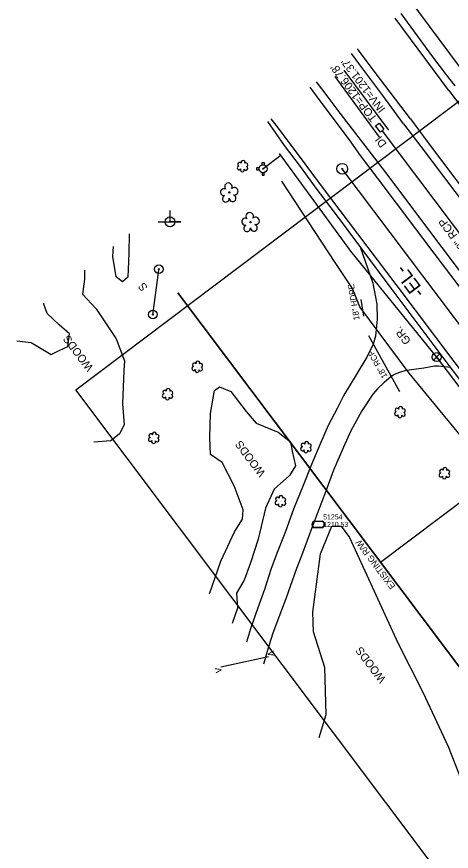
# Model space of a CAD drawing. Extents: x 1262092 to 1264624, y 774970 to 778314.
# Drawn here: x 1262092.3 to 1262309.6, y 777671.7 to 778088.7 of the extents above; entities that cross this region are included whole.
import ezdxf

# ---------------------------------------------------------------- set-up
doc = ezdxf.new("R2010")
doc.units = 0
for name, color, linetype in [('COGO Default Parcel', 7, 'Continuous'), ('Exist Boundary City Limits', 7, 'Continuous'), ('Exist Horizontal Alignment', 7, 'Continuous'), ('Exist Horizontal Alignment Direction Label', 7, 'Continuous'), ('Exist Horizontal Alignment Station Label', 7, 'Continuous'), ('Exist Horizontal Alignment Tick Label', 7, 'Continuous'), ('Exist Horizontal Alignment Tick Large', 7, 'Continuous'), ('Exist Horizontal Alignment Tick Small', 7, 'Continuous'), ('Exist Right of Way Line', 7, 'Continuous'), ('Exist Right of Way Line Text', 7, 'Continuous'), ('Exist Right of Way Width CELL', 7, 'Continuous'), ('Exist Roads EOP', 7, 'Continuous'), ('Exist Roads EOT', 7, 'Continuous'), ('Exist Roads Soil Text', 7, 'Continuous'), ('Exist Structure Minor Drop Inlet', 7, 'Continuous'), ('Exist Structure Minor Drop Inlet Text', 7, 'Continuous'), ('Exist Structure Minor Drop Inlet Top Elevation', 7, 'Continuous'), ('Exist Structure Minor Paved Ditch or Gutter', 7, 'Continuous'), ('Exist Structure Minor Pipes HDPE 18 Inch', 7, 'Continuous'), ('Exist Structure Minor Pipes HDPE 18 Inch Text', 7, 'Continuous'), ('Exist Structure Minor Pipes RCP 18 Inch', 7, 'Continuous'), ('Exist Structure Minor Pipes RCP 18 Inch Invert', 7, 'Continuous'), ('Exist Structure Minor Pipes RCP 18 Inch Text', 7, 'Continuous'), ('Exist Utilities Power Joint Use Telephone CELL', 7, 'Continuous'), ('Exist Utilities Sanitary Sewer UG Line', 7, 'Continuous'), ('Exist Utilities Telephone UG FO SUE LOS B', 7, 'Continuous'), ('Exist Utilities Water Fire Hydrant CELL', 7, 'Continuous'), ('Exist Utilities Water Meter CELL', 7, 'Continuous'), ('Exist Utilities Water Meter Cogo Elevation', 7, 'Continuous'), ('Exist Utilities Water Meter Cogo Number', 7, 'Continuous'), ('Exist Utilities Water UG Line SUE LOS B', 7, 'Continuous'), ('Exist Utilities Water Valve CELL', 7, 'Continuous'), ('Exist Vegetation Woods Line Text', 7, 'Continuous'), ('Prop Conc 5in Monolithic Keyed In Island', 7, 'Continuous'), ('Prop Conc 5in Monolithic Surface Mount Island', 7, 'Continuous'), ('Prop Horizontal Alignment Tick Small', 7, 'Continuous'), ('Prop Paved Shoulder', 7, 'Continuous'), ('Scratch_Level_1', 7, 'Continuous')]:
    doc.layers.add(name, color=color, linetype=linetype)

# ---------------------------------------------------------------- blocks, each defined once
blk = doc.blocks.new('EXIST UTILITIES WATER VALVE')
at = {"layer": 'Exist Utilities Water Valve CELL'}
blk.add_lwpolyline([(0.0315, 0.0315), (-0.0315, -0.0315), (0, 0), (0.0315, -0.0315), (-0.0315, 0.0315)], dxfattribs=at)
blk.add_circle((0, 0), 0.0445, dxfattribs=at)
blk = doc.blocks.new('EXIST UTILITIES WATER FIRE HYDRANT')
at = {"layer": 'Exist Utilities Water Fire Hydrant CELL'}
blk.add_line((0, 0), (0, 0), dxfattribs=at)
for points in [[(-0.03825, 0.01025), (-0.064, 0.01025), (-0.064, -0.01025), (-0.03825, -0.01025)], [(-0.01025, 0.03825), (-0.01025, 0.064), (0.01025, 0.064), (0.01025, 0.03775)], [(-0.01025, -0.03825), (-0.01025, -0.064), (0.01025, -0.064), (0.01025, -0.03775)]]:
    blk.add_lwpolyline(points, dxfattribs=at)
for radius in [0.03954, 0.00485]:
    blk.add_circle((0, 0), radius, dxfattribs=at)
blk = doc.blocks.new('EXIST UTILITIES WATER METER')
at = {"layer": 'Exist Utilities Water Meter CELL'}
blk.add_line((0, 0), (0, 0), dxfattribs=at)
for points in [[(-0.0408, 0.034), (0.0408, 0.034)], [(-0.0408, 0.0312), (0.0408, 0.0312)], [(0.0408, -0.0312), (-0.0413, -0.0312)], [(0.0408, -0.034), (-0.0413, -0.034)]]:
    blk.add_lwpolyline(points, dxfattribs=at)
for centre, radius, start, end in [((-0.0261, -0.0001), 0.0371, 113.17804, 245.97939), ((-0.0259, -0.0001), 0.0347, 115.30093, 243.78236), ((0.0259, 0), 0.0371, 293.64832, 66.30838), ((0.0261, 0), 0.0345, 295.12717, 64.87283)]:
    blk.add_arc(centre, radius, start, end, dxfattribs=at)

msp = doc.modelspace()

# ---------------------------------------------------------------- linework, layer by layer
at = {"layer": 'COGO Default Parcel'}
for p, q in [((1262121.77, 777902.18), (1262441.33, 778142.77)), ((1263155.86, 776528.63), (1262121.77, 777902.18))]:
    msp.add_line(p, q, dxfattribs=at)
at = {"layer": 'Exist Boundary City Limits'}
msp.add_line((1263013.39, 776834.66), (1262172.78, 777950.69), dxfattribs=at)
at = {"layer": 'Exist Horizontal Alignment'}
msp.add_line((1264460.35, 775084.79), (1262255.05, 778012.66), dxfattribs=at)
at = {"layer": 'Exist Horizontal Alignment Station Label'}
msp.add_line((1262160.42, 777939.68), (1262163.43, 777962.08), dxfattribs=at)
for centre, radius in [((1262163.35, 777962.55), 2.18), ((1262163.35, 777962.55), 0.24), ((1262160.39, 777939.84), 2.18), ((1262160.39, 777939.84), 0.24)]:
    msp.add_circle(centre, radius, dxfattribs=at)
at = {"layer": 'Exist Horizontal Alignment Tick Label'}
for radius in [2.71, 0.187]:
    msp.add_circle((1262255.05, 778012.66), radius, dxfattribs=at)
at = {"layer": 'Exist Horizontal Alignment Tick Large'}
for p, q in [((1262205.25, 778013.8), (1262205.25, 778013.8)), ((1262182.59, 777913.56), (1262182.59, 777913.56)), ((1262167.75, 777899.89), (1262167.75, 777899.89)), ((1262284, 777890.93), (1262284, 777890.93)), ((1262160.86, 777878.12), (1262160.86, 777878.12)), ((1262237, 777873.43), (1262237, 777873.43)), ((1262306.24, 777860.38), (1262306.24, 777860.38)), ((1262224.21, 777846.48), (1262224.21, 777846.48))]:
    msp.add_line(p, q, dxfattribs=at)
for centre, radius, start, end in [((1262205.48, 778015.84), 0.99, 334.8391, 200.4717), ((1262203.45, 778013.09), 0.955, 95.1099, 327.9534), ((1262203.77, 778014.92), 0.968, 35.8908, 245.4216), ((1262206.89, 778012.87), 0.937, 204.9913, 73.4601), ((1262206.92, 778014.67), 0.929, 284.4567, 126.0861), ((1262205.12, 778012.11), 0.984, 151.2797, 21.387), ((1262180.79, 777912.86), 0.955, 95.1099, 327.9534), ((1262181.11, 777914.69), 0.968, 35.8908, 245.4216), ((1262182.82, 777915.6), 0.99, 334.8391, 200.4717), ((1262184.23, 777912.63), 0.937, 204.9913, 73.4601), ((1262184.27, 777914.43), 0.929, 284.4567, 126.0861), ((1262182.47, 777911.88), 0.984, 151.2797, 21.387), ((1262165.95, 777899.18), 0.955, 95.1099, 327.9534), ((1262166.27, 777901.01), 0.968, 35.8908, 245.4216), ((1262167.98, 777901.93), 0.99, 334.8391, 200.4717), ((1262169.42, 777900.76), 0.929, 284.4567, 126.0861), ((1262167.62, 777898.2), 0.984, 151.2797, 21.387), ((1262169.39, 777898.96), 0.937, 204.9913, 73.4601), ((1262282.52, 777892.06), 0.968, 35.8908, 245.4216), ((1262284.23, 777892.97), 0.99, 334.8391, 200.4717), ((1262285.68, 777891.8), 0.929, 284.4567, 126.0861), ((1262282.2, 777890.23), 0.955, 95.1099, 327.9534), ((1262283.88, 777889.25), 0.984, 151.2797, 21.387), ((1262285.64, 777890.01), 0.937, 204.9913, 73.4601), ((1262159.38, 777879.25), 0.968, 35.8908, 245.4216), ((1262161.09, 777880.16), 0.99, 334.8391, 200.4717), ((1262162.54, 777878.99), 0.929, 284.4567, 126.0861), ((1262159.06, 777877.41), 0.955, 95.1099, 327.9534), ((1262160.73, 777876.43), 0.984, 151.2797, 21.387), ((1262162.5, 777877.19), 0.937, 204.9913, 73.4601), ((1262235.52, 777874.56), 0.968, 35.8908, 245.4216), ((1262237.23, 777875.47), 0.99, 334.8391, 200.4717), ((1262238.68, 777874.3), 0.929, 284.4567, 126.0861), ((1262235.2, 777872.72), 0.955, 95.1099, 327.9534), ((1262236.88, 777871.74), 0.984, 151.2797, 21.387), ((1262238.64, 777872.5), 0.937, 204.9913, 73.4601), ((1262306.46, 777862.42), 0.99, 334.8391, 200.4717), ((1262304.43, 777859.67), 0.955, 95.1099, 327.9534), ((1262304.75, 777861.5), 0.968, 35.8908, 245.4216), ((1262306.11, 777858.69), 0.984, 151.2797, 21.387), ((1262307.87, 777859.45), 0.937, 204.9913, 73.4601), ((1262307.91, 777861.25), 0.929, 284.4567, 126.0861), ((1262222.41, 777845.78), 0.955, 95.1099, 327.9534), ((1262222.73, 777847.61), 0.968, 35.8908, 245.4216), ((1262224.44, 777848.52), 0.99, 334.8391, 200.4717), ((1262225.85, 777845.55), 0.937, 204.9913, 73.4601), ((1262225.88, 777847.35), 0.929, 284.4567, 126.0861), ((1262224.08, 777844.8), 0.984, 151.2797, 21.387)]:
    msp.add_arc(centre, radius, start, end, dxfattribs=at)
at = {"layer": 'Exist Horizontal Alignment Tick Small'}
for p, q in [((1262198.55, 778000.85), (1262198.55, 778000.85)), ((1262209.18, 777986.05), (1262209.18, 777986.05))]:
    msp.add_line(p, q, dxfattribs=at)
for centre in [(1262198.55, 778000.85), (1262209.18, 777986.05)]:
    msp.add_circle(centre, 0.326, dxfattribs=at)
for centre, radius, start, end in [((1262198.16, 778003.72), 1.86, 330.1651, 219.7134), ((1262195.94, 778001), 1.73, 62.6636, 279.3457), ((1262201.1, 778001.44), 1.9, 257.1011, 134.1999), ((1262196.85, 777997.73), 1.69, 111.5671, 6.231), ((1262200.22, 777997.95), 1.7, 181.2822, 74.56), ((1262206.57, 777986.2), 1.73, 62.6636, 279.3457), ((1262208.79, 777988.92), 1.86, 330.1651, 219.7134), ((1262211.72, 777986.64), 1.9, 257.1011, 134.1999), ((1262207.47, 777982.93), 1.69, 111.5671, 6.231), ((1262210.85, 777983.15), 1.7, 181.2822, 74.56)]:
    msp.add_arc(centre, radius, start, end, dxfattribs=at)
at = {"layer": 'Exist Right of Way Line'}
msp.add_line((1262172.78, 777950.69), (1263224.83, 776553.94), dxfattribs=at)
at = {"layer": 'Exist Right of Way Width CELL'}
msp.add_line((1262274.14, 777816.12), (1262377.95, 777894.31), dxfattribs=at)
at = {"layer": 'Exist Roads EOP'}
for points in [[(1262311.57, 778054.09), (1262307.15, 778059.68), (1262299.95, 778069.33), (1262289.62, 778083.4), (1262284.54, 778090.33)], [(1262285.77, 778035.09), (1262275.45, 778049.22), (1262263.83, 778064.64), (1262259.68, 778070.19)], [(1262268.09, 778022.33), (1262253.95, 778040.53), (1262247.45, 778049.14), (1262242.22, 778056.05)], [(1262242.02, 778002.99), (1262234.65, 778013.07), (1262226.25, 778024.29), (1262217.88, 778036.33)], [(1262285.77, 778035.09), (1262294.3, 778023.82), (1262322.73, 777986.32), (1262351.06, 777948.49), (1262379.86, 777910.83), (1262408.98, 777872.17), (1262437.51, 777834.34), (1262465.79, 777796.98), (1262494.21, 777759.25), (1262523.56, 777720.28), (1262551.17, 777683.56), (1262580.06, 777645.73)], [(1262533.86, 777669.85), (1262506.16, 777706.68), (1262477.25, 777744.96), (1262448.83, 777782.76), (1262448.77, 777782.75), (1262419.94, 777820.99), (1262391.44, 777858.59), (1262362.67, 777897.37), (1262333.74, 777935.31), (1262305.02, 777973.3), (1262276.84, 778010.82), (1262268.09, 778022.33)], [(1262508.59, 777649.5), (1262480.62, 777686.61), (1262451.55, 777725.45), (1262423.03, 777763.23), (1262394.37, 777801.14), (1262366.02, 777838.6), (1262337.3, 777876.52), (1262308.59, 777914.31), (1262279.57, 777952.95), (1262251.16, 777991.02), (1262242.02, 778002.99)]]:
    msp.add_lwpolyline(points, dxfattribs=at)
at = {"layer": 'Exist Roads EOT'}
for points in [[(1262308.34, 778051.79), (1262293.03, 778072.51), (1262281.51, 778087.87)], [(1262289.2, 778037.57), (1262271.58, 778060.8), (1262262.68, 778072.62)], [(1262264.28, 778019.28), (1262258.72, 778027.11), (1262243.53, 778047.28), (1262238.95, 778053.39)], [(1262308.34, 778051.79), (1262317.32, 778039.93), (1262344.37, 778004.19), (1262372.89, 777966.62), (1262401.21, 777929.2), (1262429.93, 777891.21), (1262458.73, 777853.38), (1262487.94, 777814.62), (1262517.12, 777776.18), (1262546.22, 777737.8), (1262573.92, 777700.82), (1262602.3, 777663.12)], [(1262244.27, 778004.78), (1262232.65, 778020.23), (1262221.97, 778034.53), (1262219.58, 778037.7)], [(1262289.2, 778037.57), (1262297.52, 778026.31), (1262325.76, 777988.99), (1262354.59, 777951.12), (1262382.95, 777913.24), (1262412.22, 777874.41), (1262440.97, 777836.5), (1262469.27, 777799.15), (1262497.42, 777761.79), (1262526.95, 777722.8), (1262554.72, 777686.15), (1262583.3, 777648.11)], [(1262530.21, 777667.14), (1262502.53, 777703.54), (1262473.57, 777742.17), (1262445.07, 777779.99), (1262416.17, 777818.02), (1262387.95, 777855.59), (1262358.59, 777894.64), (1262330.16, 777932.09), (1262301.01, 777970.53), (1262273.04, 778007.62), (1262264.28, 778019.28)], [(1262511.28, 777651.42), (1262483.32, 777688.89), (1262454.05, 777727.36), (1262425.45, 777765.13), (1262396.78, 777803.08), (1262368.42, 777840.5), (1262339.71, 777878.55), (1262311.54, 777915.71), (1262282.01, 777954.91), (1262253.58, 777992.51), (1262244.27, 778004.78)]]:
    msp.add_lwpolyline(points, dxfattribs=at)
at = {"layer": 'Exist Structure Minor Drop Inlet'}
msp.add_lwpolyline([(1262275.95, 778032.42), (1262274.13, 778031.01), (1262271.73, 778034.1), (1262273.55, 778035.51), (1262275.95, 778032.42)], dxfattribs=at)
at = {"layer": 'Exist Structure Minor Paved Ditch or Gutter'}
for p, q in [((1262273.73, 778028.5), (1262251.46, 778058.71)), ((1262278.42, 778031.97), (1262256, 778062))]:
    msp.add_line(p, q, dxfattribs=at)
at = {"layer": 'Exist Structure Minor Pipes HDPE 18 Inch'}
msp.add_line((1262264.3, 777947.43), (1262265.64, 777939.06), dxfattribs=at)
at = {"layer": 'Exist Structure Minor Pipes RCP 18 Inch'}
for p, q in [((1262514.1, 777714.3), (1262275, 778031.81)), ((1262283.95, 777901.25), (1262268.3, 777929.16))]:
    msp.add_line(p, q, dxfattribs=at)
at = {"layer": 'Exist Utilities Power Joint Use Telephone CELL'}
msp.add_line((1262168.96, 777986.16), (1262168.96, 777986.16), dxfattribs=at)
msp.add_lwpolyline([(1262163.02, 777986.16), (1262174.36, 777986.12), (1262168.96, 777986.14), (1262168.96, 777991.78)], dxfattribs=at)
msp.add_circle((1262168.96, 777986.16), 2.45, dxfattribs=at)
at = {"layer": 'Exist Utilities Sanitary Sewer UG Line'}
msp.add_line((1262150.97, 778282.31), (1262537.27, 777762.91), dxfattribs=at)
at = {"layer": 'Exist Utilities Telephone UG FO SUE LOS B'}
msp.add_lwpolyline([(1262497.69, 777644.72), (1262472.81, 777678.82), (1262454.22, 777702.45), (1262410.39, 777767.02), (1262381.85, 777803.45), (1262346.33, 777843.25), (1262319.52, 777872.83), (1262288.46, 777910.54), (1262263.91, 777943.64), (1262260.24, 777952.77), (1262251.56, 777965.81), (1262224.91, 778006.43)], dxfattribs=at)
at = {"layer": 'Exist Utilities Water UG Line SUE LOS B'}
msp.add_line((1262224.43, 778019.24), (1262215.47, 778012.68), dxfattribs=at)
msp.add_lwpolyline([(1262961.53, 777041.32), (1262916.91, 777099.45), (1262892.75, 777131.3), (1262862.6, 777171.1), (1262817.98, 777226.85), (1262789.55, 777268.74), (1262774.27, 777287.66), (1262763.83, 777305.05), (1262732.33, 777346.94), (1262685.88, 777410.11), (1262660.87, 777443.18), (1262632.31, 777481.08), (1262598.3, 777526.4), (1262560.14, 777576.52), (1262506.51, 777647.45), (1262479.01, 777683.48), (1262453.07, 777718.25), (1262416.94, 777766.02), (1262382.77, 777811.78), (1262358.61, 777844.73), (1262327.38, 777885.68), (1262302.32, 777918.54), (1262259.45, 777971.43), (1262223.66, 778020.3)], dxfattribs=at)
at = {"layer": 'Prop Conc 5in Monolithic Keyed In Island'}
for points in [[(1262148.48, 777980.09), (1262148.38, 777970.54), (1262147.92, 777958.5), (1262145.15, 777956.26), (1262141.94, 777958.67), (1262140.4, 777968.87), (1262140.73, 777973.82)], [(1262126.22, 777962.06), (1262126.2, 777957.44), (1262125.1, 777950.08), (1262132.04, 777942.64), (1262142.04, 777927.73), (1262146.11, 777916.75), (1262145.89, 777911.8), (1262145.26, 777895.21), (1262146.06, 777884.81), (1262143.76, 777880.27), (1262139.27, 777876.76), (1262130.87, 777876.12)], [(1262092.26, 777926.7), (1262099.45, 777925.9), (1262109.44, 777919.84), (1262113.53, 777921.82), (1262117.89, 777923.81), (1262118.69, 777930.26), (1262113.47, 777934.71), (1262107.49, 777940.38), (1262105.84, 777945), (1262105.82, 777945.54)], [(1262188.74, 777800.31), (1262194.36, 777816.62), (1262201.21, 777831.27), (1262205.19, 777837.6), (1262205.48, 777842.24), (1262200.95, 777854.3), (1262194.95, 777865.97), (1262189.22, 777869.87), (1262188.84, 777878.27), (1262189.21, 777890.43), (1262191.21, 777901.83), (1262193.72, 777903.7), (1262199.29, 777901.45), (1262206.95, 777891.36), (1262211.99, 777885.53), (1262223.04, 777881.14), (1262229.22, 777876.16), (1262229.96, 777871.57), (1262231.72, 777864.19), (1262228.68, 777859.45), (1262221.04, 777852.55), (1262216.69, 777843.12), (1262212.97, 777827.6), (1262209.18, 777815.74), (1262206.06, 777807.05), (1262202.16, 777800.61), (1262202.69, 777793.21), (1262200.06, 777785.48)], [(1262243.57, 777728.49), (1262247.11, 777740.03), (1262246.4, 777763.43), (1262240.71, 777781.37), (1262240.42, 777791.08), (1262244.13, 777820.23), (1262249.84, 777834.04), (1262254.54, 777834.16), (1262258.78, 777828.44), (1262269.13, 777805.64), (1262282.81, 777775.74), (1262295.35, 777751.2), (1262308.02, 777724.09), (1262316.51, 777702.39), (1262324.71, 777681.54), (1262329.36, 777676.47), (1262339.85, 777668.31)]]:
    msp.add_lwpolyline(points, dxfattribs=at)
at = {"layer": 'Prop Conc 5in Monolithic Surface Mount Island'}
msp.add_line((1262218.23, 777768.8), (1262194.38, 777763.74), dxfattribs=at)
at = {"layer": 'Prop Horizontal Alignment Tick Small'}
for points in [[(1262264.11, 777973.67), (1262270.42, 777955.44), (1262272.33, 777944.94), (1262272.56, 777937.56), (1262271.76, 777929.01), (1262270.48, 777925.11), (1262267.43, 777918.49), (1262261.96, 777909.71), (1262255.94, 777899.62), (1262252.55, 777892.95), (1262248.08, 777884.38), (1262244.23, 777875.57), (1262239.7, 777864.87), (1262235.51, 777854.47), (1262230.76, 777842.57), (1262226.64, 777831.47), (1262222.49, 777820.91), (1262219.43, 777812.39), (1262216.17, 777802.49), (1262212.81, 777793.38), (1262209.22, 777782.82), (1262207.21, 777776.12)], [(1262309.29, 777913.38), (1262303.26, 777914.08), (1262301.18, 777913.99), (1262295.89, 777913.08), (1262289.71, 777912.29), (1262286.36, 777911.74), (1262284.17, 777911.08), (1262281.91, 777910.26), (1262280.58, 777909.54), (1262279.41, 777908.67), (1262276.05, 777905.87), (1262272.78, 777902.7), (1262270.31, 777900.06), (1262264.8, 777891.69), (1262259.43, 777881.82), (1262255.74, 777873.61), (1262250.77, 777862.15), (1262246.81, 777851.54), (1262240.42, 777834.56), (1262234.63, 777819.24), (1262232.15, 777813.01), (1262226.86, 777797.81), (1262223.81, 777789.93), (1262220.22, 777780.23), (1262217.87, 777772.72), (1262215.84, 777765.67), (1262215.63, 777765.09)]]:
    msp.add_lwpolyline(points, dxfattribs=at)

# ---------------------------------------------------------------- block references
at = {"layer": 'Exist Utilities Water Fire Hydrant CELL', "xscale": 50, "yscale": 50}
msp.add_blockref('EXIST UTILITIES WATER FIRE HYDRANT', (1262215.47, 778012.68), dxfattribs=at)
at = {"layer": 'Exist Utilities Water Meter CELL', "xscale": 50, "yscale": 50}
msp.add_blockref('EXIST UTILITIES WATER METER', (1262243.07, 777834.98), dxfattribs=at)
at = {"layer": 'Exist Utilities Water Valve CELL', "xscale": 50, "yscale": 50}
msp.add_blockref('EXIST UTILITIES WATER VALVE', (1262302.31, 777918.57), dxfattribs=at)

# ---------------------------------------------------------------- texts
at = {"layer": 'Exist Horizontal Alignment Direction Label'}
msp.add_text('-EL-', height=7, rotation=126.9874, dxfattribs=at).set_placement((1262296.71, 777951.16))
at = {"layer": 'Exist Right of Way Line Text'}
msp.add_text('EXISTING R/W', height=3.2, rotation=126.9874, dxfattribs=at).set_placement((1262281.84, 777804.13))
at = {"layer": 'Exist Roads Soil Text'}
msp.add_text('GR.', height=4, rotation=126.9874, dxfattribs=at).set_placement((1262289.62, 777926.69))
at = {"layer": 'Exist Structure Minor Drop Inlet Text'}
msp.add_text('DI', height=4, rotation=126.9874, dxfattribs=at).set_placement((1262277.56, 778025.15))
at = {"layer": 'Exist Structure Minor Drop Inlet Top Elevation'}
msp.add_text("TOP=1206.78'", height=4, rotation=126.9874, dxfattribs=at).set_placement((1262272.78, 778037.97))
at = {"layer": 'Exist Structure Minor Pipes HDPE 18 Inch Text'}
msp.add_text('18" HDPE', height=3, rotation=99.1234, dxfattribs=at).set_placement((1262263.78, 777937.32))
at = {"layer": 'Exist Structure Minor Pipes RCP 18 Inch Invert'}
msp.add_text("INV=1201.37'", height=4, rotation=126.9874, dxfattribs=at).set_placement((1262276.82, 778042.55))
at = {"layer": 'Exist Structure Minor Pipes RCP 18 Inch Text'}
for height, rotation, p in [(4, 126.9805, (1262318.47, 777972.03)), (3, 119.2684, (1262277.79, 777908.99))]:
    msp.add_text('18" RCP', height=height, rotation=rotation, dxfattribs=at).set_placement(p)
at = {"layer": 'Exist Utilities Water Meter Cogo Elevation'}
msp.add_text('1210.53', height=2.5, dxfattribs=at).set_placement((1262245.57, 777833.73))
at = {"layer": 'Exist Utilities Water Meter Cogo Number'}
msp.add_text('51254', height=2.5, dxfattribs=at).set_placement((1262245.57, 777837.48))
at = {"layer": 'Exist Vegetation Woods Line Text'}
for p in [(1262130.83, 777913.38), (1262216.9, 777860.68), (1262277.13, 777757.67)]:
    msp.add_text('WOODS', height=4, rotation=126.9874, dxfattribs=at).set_placement(p)
at = {"layer": 'Prop Paved Shoulder'}
msp.add_text('S', height=4, rotation=126.9874, dxfattribs=at).set_placement((1262158.01, 777953.37))
at = {"layer": 'Scratch_Level_1'}
for rotation, p in [(281.9925, (1262217.68, 777771.39)), (101.9925, (1262194.93, 777761.15))]:
    msp.add_text('v', height=4, rotation=rotation, dxfattribs=at).set_placement(p)

doc.saveas('drawing.dxf')
